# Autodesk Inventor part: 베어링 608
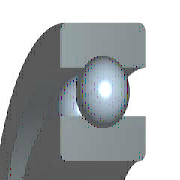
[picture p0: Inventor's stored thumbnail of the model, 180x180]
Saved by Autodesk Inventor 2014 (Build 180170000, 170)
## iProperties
IsCustomPart: 1
Created: 2012-02
Part Number: 베어링 608
Material: 강철, 연강
Description: 깊은 그루브 볼 베어링
Document SubType Name: Modeling
Standard: KS B 2023
Designer: mduedu
Standards Organization: KS
Language: ko-KR
Size Designation: 608 - 8 x 22 x 7
Categories: <MemberInstance><Categories><Category DisplayName="샤프트 부품" InternalName="7f7aeb1f-a693-4053-b835-cee3144e0d98" Mnemonic="SHFT"><Category DisplayName="베어링" Inter
Density: 7.86 g/cm^3
Mass: 12.1605 g
Surface Area: 20.0754 cm^2
Volume: 1.54714 cm^3
Appearance: 노란색
Author: mduedu
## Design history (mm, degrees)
sketch "스케치" dims "d0" = 3.64 (= -0.26 x WD + 0.26 x BD)
  geometry: L1 (1.68, 7.5)-(5.32, 7.5); L2 (3.5, 7.5)-(3.5, 5.68); L3 (3.5, 7.5)-(3.5, 9.32); L4 (2.148, 6.282)-(0, 6.282); L5 (0, 4)-(7, 4); L6 (2.148, 8.718)-(0, 8.718); L7 (0, 11)-(7, 11); L8 (7, 4)-(7, 6.282); L9 (4.852, 6.282)-(7, 6.282); L10 (4.852, 8.718)-(7, 8.718); L11 (7, 11)-(7, 8.718); L12 (-1.4, 0)-(8.4, 0) reference; L13 (0, -0.3)-(0, 5.3) reference
  constraints: 22 end point, 4 point on line, 2 collinear, 2 perpendicular, 2 symmetric about line, 1 midpoint, 1 parallel, 14 other
  dimensions: "d9" = 8 diameter of L5 L12 (= WD); "d11" = 22 diameter of L7 L12 (= BD); "d12" = 7 distance between parallel lines of L8 L13 (= KB); "d13" = 12.564 diameter of L9 L12 (= 0.326 x BD + 0.674 x WD)
revolve "본체" stored, may be unused: angle "d6" = 90 deg
revolve "볼" stored, may be unused: angle "d7" = 90 deg
pattern_circular "IDS_ARRAYBALL[SIMPL:T]" dims angle "d3" = 360 deg
body "Solid1"
fillet "모깎기1" dims "d1" = 0.3 (= KRS)
other parameters: "WD" = 8 [user parameter; used in 5 equation terms], "BD" = 22 [user parameter; used in 5 equation terms], "KB" = 7 [user parameter; used in 1 equation term], "KRS" = 0.3 [user parameter; used in 1 equation term], "d4" = 0, "d5" = 0, "d8" = 0, "d14" = 0, "d15" = 0, "BBA" = 0 [user parameter], "BC0" = 1370000 [user parameter], "BC" = 3250000 [user parameter], "BR" = 11 (= 0.5 x BD) [user parameter], "WR" = 4 (= 0.5 x WD) [user parameter]
